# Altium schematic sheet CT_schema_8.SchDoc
size 368 x 333 mm
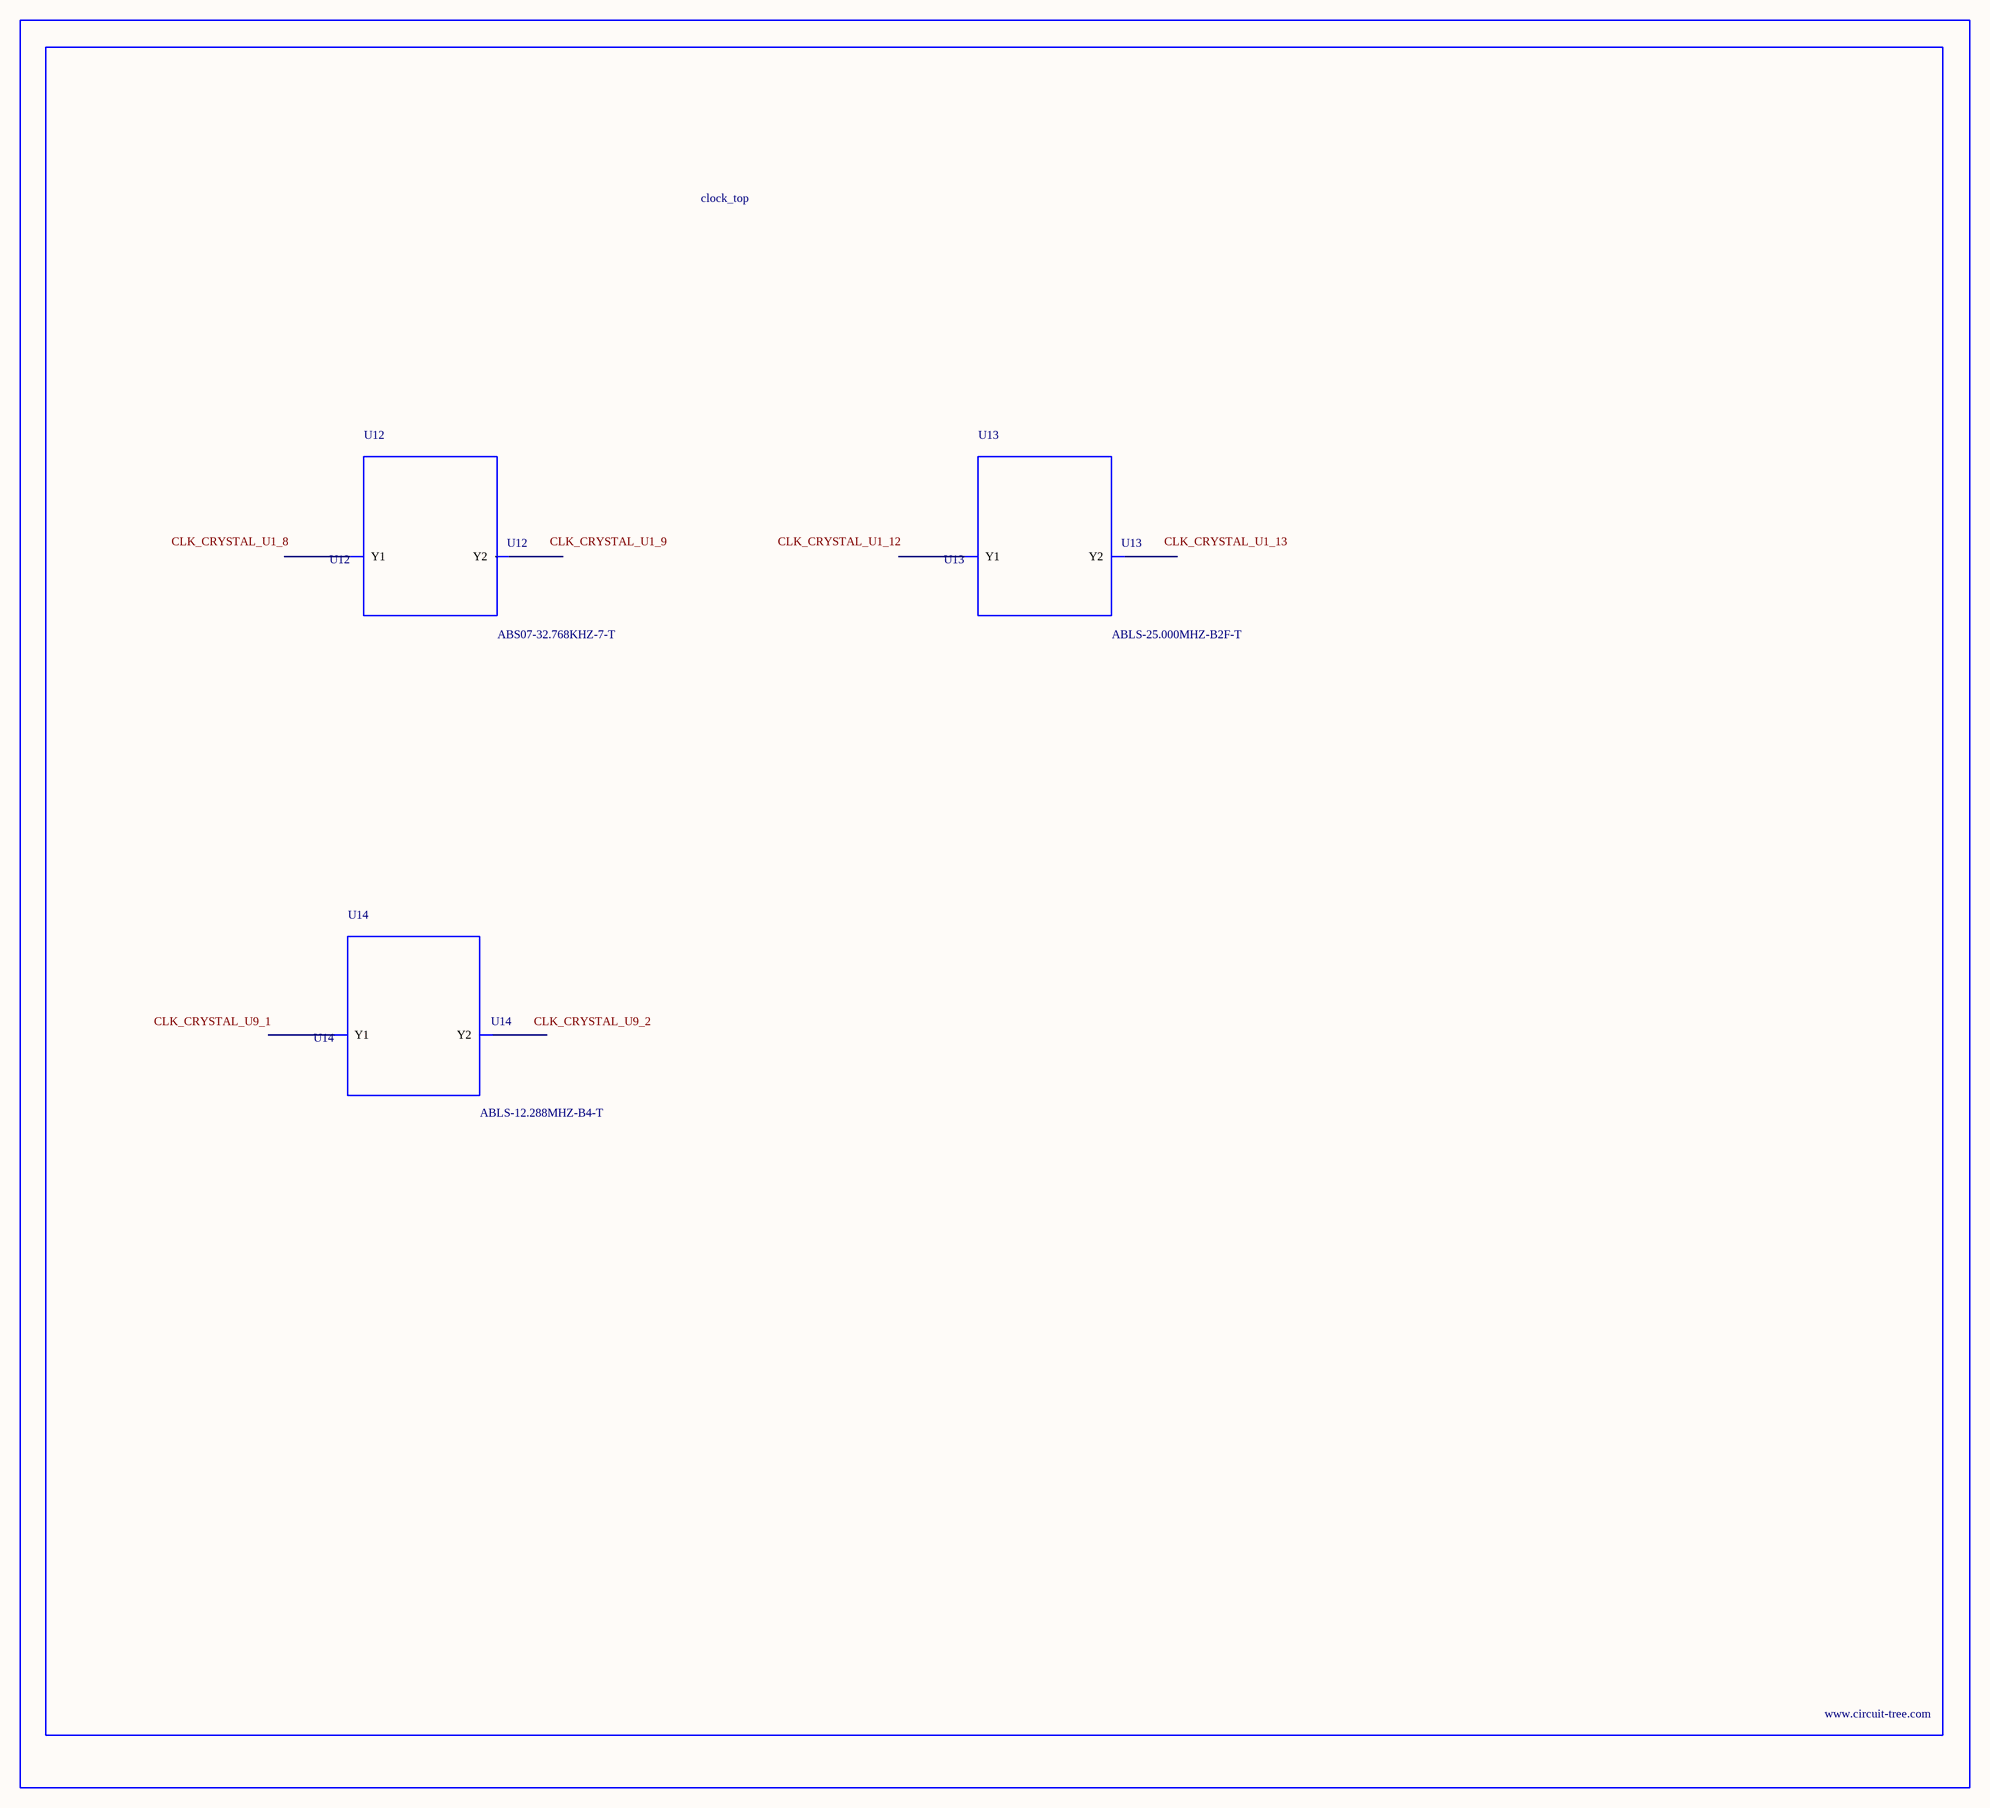
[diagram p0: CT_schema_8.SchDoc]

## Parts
BORDER7  (no value)
U12  ABS07-32.768KHZ-7-T  [ABS07-32.768KHZ-7-T]
U13  ABLS-25.000MHZ-B2F-T  [ABLS-25.000MHZ-B2F-T]
U14  ABLS-12.288MHZ-B4-T  [ABLS-12.288MHZ-B4-T]

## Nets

Not connected (* = marked no-connect by the designer): U12 1(Y1) 2(Y2); U13 1(Y1) 2(Y2); U14 1(Y1) 2(Y2)

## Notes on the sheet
- Labels drawn without touching a wire or pin: CLK_CRYSTAL_U1_8, CLK_CRYSTAL_U1_9, CLK_CRYSTAL_U1_12, CLK_CRYSTAL_U1_13, CLK_CRYSTAL_U9_1, CLK_CRYSTAL_U9_2

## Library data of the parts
BORDER7 = BORDER_PAGE7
